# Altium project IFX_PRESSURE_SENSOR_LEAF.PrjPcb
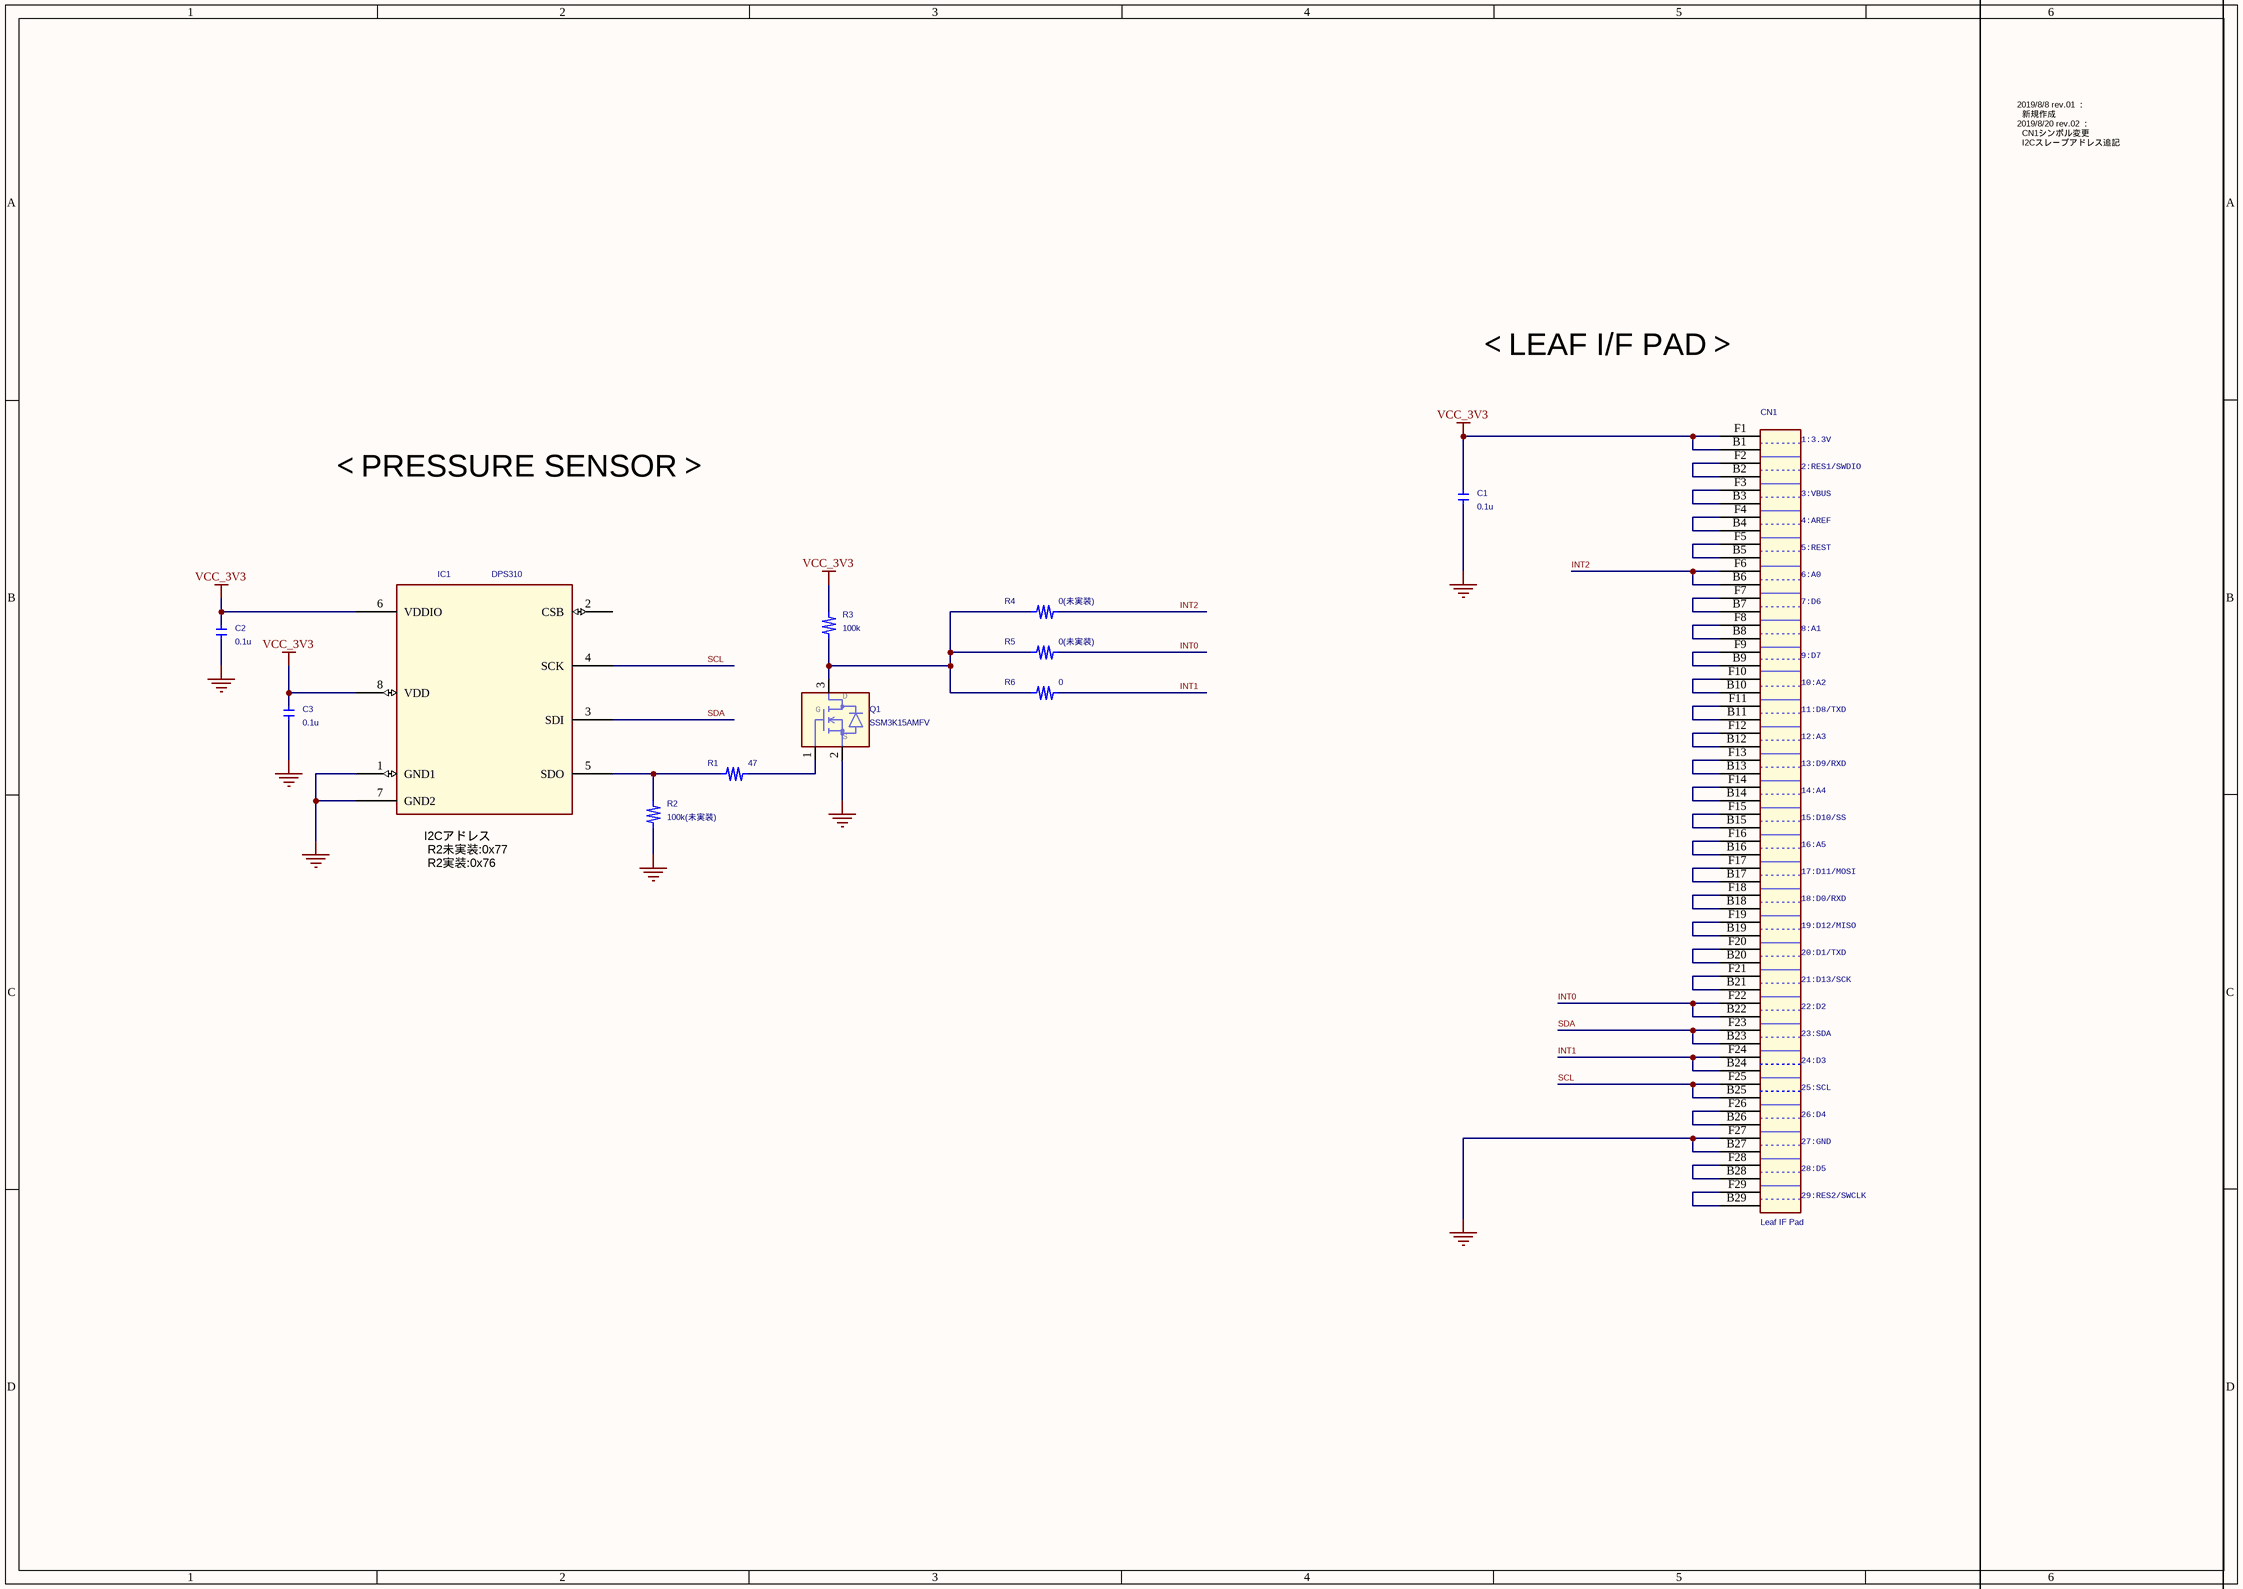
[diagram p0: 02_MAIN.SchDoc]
1 sheet, 13 parts. Net scope: global (net labels, ports and power ports of the same name join across sheets).
Board file: 02_MAIN.PcbDoc

## Sheet 02_MAIN.SchDoc
size 420 x 297 mm

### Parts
*  Confidential: NEXTY Electronics Corporation Confidential  RevCode: 02  Page Size: A3  Page Number: 3  Project Name: Trillion Node  Project ID: REF051  Sheet Name: MAIN  Schematic No.: REF051-SCH013  (hidden comment: TitleBlock_NEXTY-Ele)  (graphical)
C1  0.1u  [C-1005]
C2  0.1u  [C-1005]
C3  0.1u  [C-1005]
CN1  Leaf IF Pad  [LEAF_PAD_REV2]
IC1  DPS310  [PG-VLGA-8]
Q1  SSM3K15AMFV  [SOT-723]
R1  47  [R-1005]
R2  100k(未実装)  [R-1005]
R3  100k  [R-1005]
R4  0(未実装)  [R-1005]
R5  0(未実装)  [R-1005]
R6  0  [R-1005]

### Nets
GND: C1.2 C2.2 C3.2 CN1.B27 CN1.F27 IC1.1(GND1) IC1.7(GND2) Q1.2(S) R2.2
VCC_3V3: C1.1 C2.1 C3.1 CN1.B1 CN1.F1 IC1.6(VDDIO) IC1.8(VDD) R3.1
INT0: CN1.B22 CN1.F22 R5.2
INT1: CN1.B24 CN1.F24 R6.2
INT2: CN1.B6 CN1.F6 R4.2
SCL: CN1.B25 CN1.F25 IC1.4(SCK)
SDA: CN1.B23 CN1.F23 IC1.3(SDI)
NetCN1_B2: CN1.B2 CN1.F2
NetCN1_B3: CN1.B3 CN1.F3
NetCN1_B4: CN1.B4 CN1.F4
NetCN1_B5: CN1.B5 CN1.F5
NetCN1_B7: CN1.B7 CN1.F7
NetCN1_B8: CN1.B8 CN1.F8
NetCN1_B9: CN1.B9 CN1.F9
NetCN1_B10: CN1.B10 CN1.F10
NetCN1_B11: CN1.B11 CN1.F11
NetCN1_B12: CN1.B12 CN1.F12
NetCN1_B13: CN1.B13 CN1.F13
NetCN1_B14: CN1.B14 CN1.F14
NetCN1_B15: CN1.B15 CN1.F15
NetCN1_B16: CN1.B16 CN1.F16
NetCN1_B17: CN1.B17 CN1.F17
NetCN1_B18: CN1.B18 CN1.F18
NetCN1_B19: CN1.B19 CN1.F19
NetCN1_B20: CN1.B20 CN1.F20
NetCN1_B21: CN1.B21 CN1.F21
NetCN1_B26: CN1.B26 CN1.F26
NetCN1_B28: CN1.B28 CN1.F28
NetCN1_B29: CN1.B29 CN1.F29
NetIC1_5: IC1.5(SDO) R1.1 R2.1
NetQ1_1: Q1.1(G) R1.2
NetQ1_3: Q1.3(D) R3.2 R4.1 R5.1 R6.1

Not connected (* = marked no-connect by the designer): IC1 2(CSB)

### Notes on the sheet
- 2019/8/8 rev.01 ：
  新規作成
  2019/8/20 rev.02 ：
  CN1シンボル変更
  I2Cスレーブアドレス追記
- ＜LEAF I/F PAD＞
- ＜PRESSURE SENSOR＞
- (near IC1) I2Cアドレス
  R2未実装:0x77
  R2実装:0x76

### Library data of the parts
* = TitleBlock_NEXTY-Ele: Sample: 例; Histry_First: 完成___Rev1.0; Date2: △△△△年△△月△△日; RevChange: Rev1.0 → 1.1; Histry: B-3_Net___PG0 → PG1; date_drawn: (     /    /   )
C1-C3 = C
CN1 = Leaf_IF_Pad2
IC1 = IFX@DPS310
Q1 = TOSHIBA@SSM3K15AMFV
R1-R6 = R_chip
